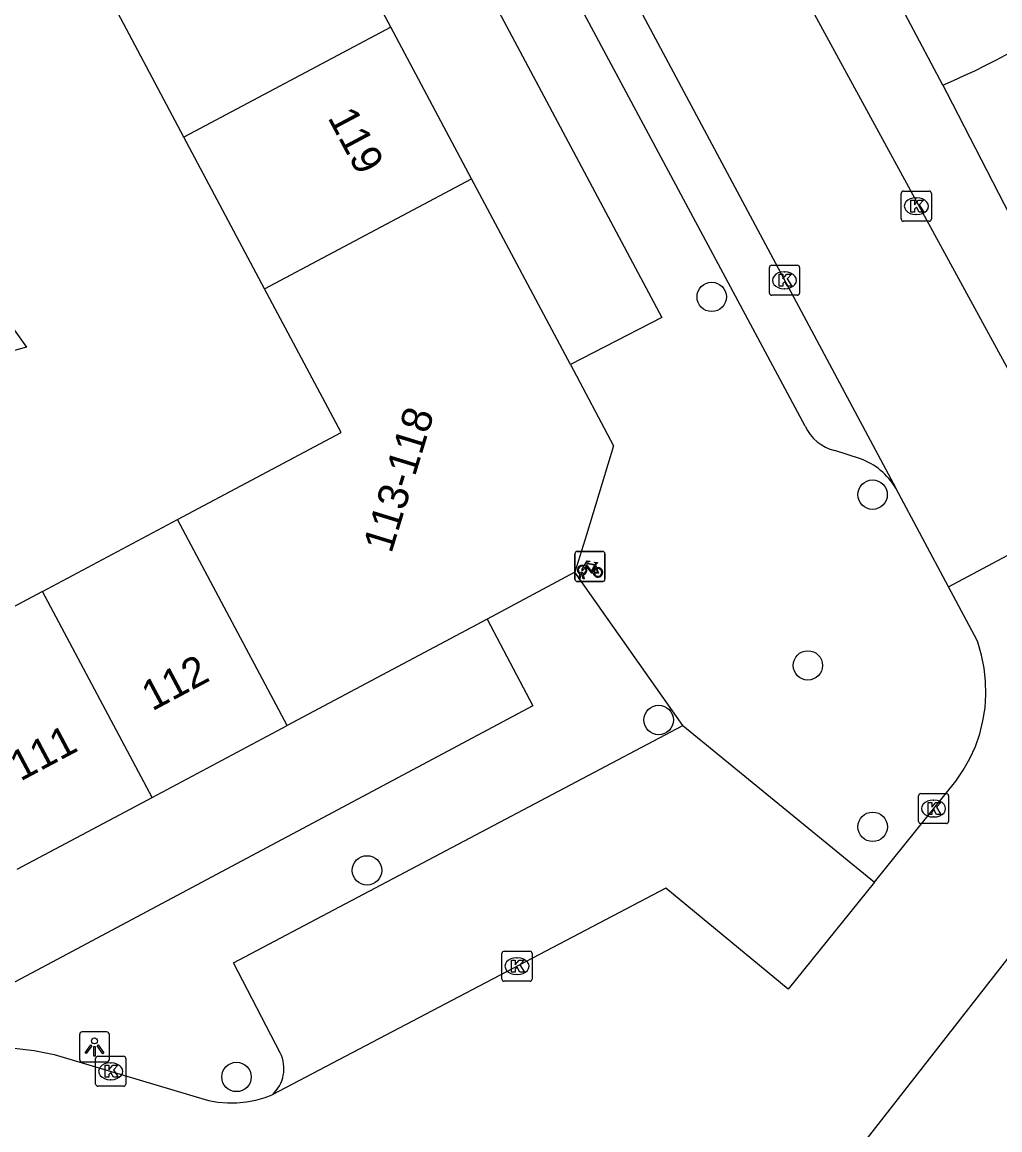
# Model space of a CAD drawing. Extents: x 160304 to 160954, y 383686 to 384161.
# Drawn here: x 160780.26 to 160812.8, y 383795.32 to 383832.18 of the extents above; entities that cross this region are included whole.
import ezdxf

# ---------------------------------------------------------------- set-up
doc = ezdxf.new("R2010")
doc.units = 0
for name, color, linetype in [('IMGEO_Boom', 7, 'Continuous'), ('IMGEO_Fietsenrek', 7, 'Continuous'), ('IMGEO_Kolk', 7, 'Continuous'), ('IMGEO_Lichtpunt', 7, 'Continuous'), ('IMGEO_Pand', 7, 'Continuous'), ('IMGEO_Pand_nummerreeks', 7, 'Continuous'), ('IMGEO_Parkeervlak_open', 7, 'Continuous'), ('IMGEO_Rijbaan_lokaal_open', 7, 'Continuous'), ('IMGEO_Voetpad_open', 7, 'Continuous')]:
    doc.layers.add(name, color=color, linetype=linetype)

msp = doc.modelspace()

# ---------------------------------------------------------------- linework, layer by layer
at = {"layer": 'IMGEO_Boom'}
for centre in [(160803.211, 383823.035), (160808.565, 383816.455), (160806.411, 383810.774), (160801.446, 383808.959), (160808.567, 383805.405), (160791.74, 383803.956), (160787.397, 383797.083)]:
    msp.add_circle(centre, 0.489, dxfattribs=at)
at = {"layer": 'IMGEO_Fietsenrek'}
for p, q in [((160798.659, 383813.642), (160798.659, 383814.483)), ((160798.659, 383814.483), (160798.659, 383813.642)), ((160798.734, 383814.567), (160799.575, 383814.567)), ((160799.575, 383814.567), (160798.734, 383814.567)), ((160799.659, 383814.492), (160799.659, 383813.651)), ((160799.659, 383813.651), (160799.659, 383814.492)), ((160799.346, 383814.116), (160799.382, 383814.021)), ((160798.786, 383813.651), (160798.825, 383813.811)), ((160798.855, 383813.799), (160798.82, 383813.651)), ((160798.897, 383813.823), (160798.896, 383813.827)), ((160798.938, 383813.651), (160798.904, 383813.793)), ((160798.928, 383813.834), (160798.929, 383813.827)), ((160798.936, 383813.797), (160798.971, 383813.651)), ((160799.584, 383813.567), (160798.743, 383813.567)), ((160798.743, 383813.567), (160799.584, 383813.567)), ((160798.82, 383813.651), (160798.786, 383813.651)), ((160798.971, 383813.651), (160798.938, 383813.651))]:
    msp.add_line(p, q, dxfattribs=at)
for points in [[(160798.993, 383814.041), (160798.941, 383813.951), (160798.901, 383813.926), (160798.902, 383813.973), (160798.957, 383814.067)], [(160798.972, 383814.093), (160799.067, 383814.257), (160799.153, 383814.243), (160799.155, 383814.234), (160799.099, 383814.223), (160799.072, 383814.178), (160799.328, 383814.137)], [(160799.268, 383813.849), (160799.218, 383813.849), (160799.027, 383814.1), (160799.008, 383814.068)], [(160799.315, 383814.112), (160799.058, 383814.153), (160799.041, 383814.124), (160799.208, 383813.904), (160799.315, 383814.112)], [(160799.363, 383814.014), (160799.333, 383814.091), (160799.224, 383813.873), (160799.267, 383813.873)], [(160799.328, 383814.137), (160799.353, 383814.186), (160799.347, 383814.19), (160799.324, 383814.194), (160799.312, 383814.201), (160799.311, 383814.204), (160799.313, 383814.209), (160799.408, 383814.194), (160799.41, 383814.184), (160799.4, 383814.171), (160799.388, 383814.165), (160799.374, 383814.171), (160799.346, 383814.116)], [(160799.297, 383813.873), (160799.417, 383813.872), (160799.373, 383813.986)], [(160799.393, 383813.993), (160799.448, 383813.848), (160799.298, 383813.848)]]:
    msp.add_lwpolyline(points, dxfattribs=at)
for centre, radius, start, end in [((160798.737, 383814.489), 0.0779, 92.4484, 184.2845), ((160798.737, 383814.489), 0.0779, 92.4484, 184.2845), ((160799.581, 383814.489), 0.0779, 2.4484, 94.2845), ((160799.581, 383814.489), 0.0779, 2.4484, 94.2845), ((160798.899, 383813.952), 0.159, 62.6766, 242.1369), ((160798.899, 383813.952), 0.129, 63.3192, 238.903), ((160798.899, 383813.952), 0.159, 283.5766, 46.6042), ((160798.879, 383813.823), 0.0499, 12.8025, 158.6934), ((160798.899, 383813.952), 0.159, 253.9967, 271.7867), ((160798.879, 383813.823), 0.0174, 12.8025, 163.4502), ((160798.899, 383813.952), 0.129, 253.415, 269.0204), ((160798.899, 383813.952), 0.129, 283.6043, 43.4302), ((160799.426, 383813.868), 0.159, 113.3408, 178.3217), ((160799.426, 383813.868), 0.159, 187.0065, 105.7708), ((160799.426, 383813.868), 0.129, 113.923, 177.9556), ((160799.426, 383813.868), 0.129, 188.6715, 104.5883), ((160798.737, 383813.645), 0.0779, 182.4484, 274.2845), ((160798.737, 383813.645), 0.0779, 182.4484, 274.2845), ((160799.581, 383813.645), 0.0779, 272.4484, 4.2845), ((160799.581, 383813.645), 0.0779, 272.4484, 4.2845)]:
    msp.add_arc(centre, radius, start, end, dxfattribs=at)
at = {"layer": 'IMGEO_Kolk'}
for p, q in [((160809.52, 383825.628), (160809.52, 383826.48)), ((160809.595, 383826.554), (160810.447, 383826.554)), ((160810.008, 383826.334), (160810.033, 383826.334)), ((160810.521, 383826.48), (160810.521, 383825.628)), ((160810.447, 383825.554), (160809.595, 383825.554)), ((160810.031, 383825.774), (160810.006, 383825.774)), ((160805.132, 383823.162), (160805.132, 383824.014)), ((160805.207, 383824.088), (160806.059, 383824.088)), ((160806.133, 383824.014), (160806.133, 383823.162)), ((160805.62, 383823.868), (160805.645, 383823.868)), ((160805.643, 383823.308), (160805.618, 383823.308)), ((160806.059, 383823.088), (160805.207, 383823.088)), ((160810.094, 383805.586), (160810.094, 383806.438)), ((160810.169, 383806.512), (160811.021, 383806.512)), ((160811.095, 383806.438), (160811.095, 383805.586)), ((160810.582, 383806.292), (160810.607, 383806.292)), ((160810.605, 383805.732), (160810.58, 383805.732)), ((160811.021, 383805.512), (160810.169, 383805.512)), ((160796.231, 383800.342), (160796.231, 383801.194)), ((160796.306, 383801.268), (160797.158, 383801.268)), ((160797.232, 383801.194), (160797.232, 383800.342)), ((160796.719, 383801.048), (160796.744, 383801.048)), ((160796.742, 383800.488), (160796.717, 383800.488)), ((160797.158, 383800.268), (160796.306, 383800.268)), ((160782.71, 383796.846), (160782.71, 383797.698)), ((160782.785, 383797.772), (160783.637, 383797.772)), ((160783.198, 383797.552), (160783.223, 383797.552)), ((160783.711, 383797.698), (160783.711, 383796.846)), ((160783.637, 383796.772), (160782.785, 383796.772)), ((160783.221, 383796.992), (160783.196, 383796.992))]:
    msp.add_line(p, q, dxfattribs=at)
for points in [[(160809.52, 383825.628), (160809.52, 383826.48)], [(160809.595, 383826.554), (160810.447, 383826.554)], [(160809.841, 383826.254), (160809.964, 383826.254), (160809.964, 383826.103), (160810.094, 383826.254), (160810.258, 383826.254), (160810.112, 383826.103), (160810.265, 383825.854), (160810.113, 383825.854), (160810.028, 383826.018), (160809.964, 383825.951), (160809.964, 383825.854), (160809.841, 383825.854), (160809.841, 383826.254)], [(160810.521, 383826.48), (160810.521, 383825.628)], [(160810.447, 383825.554), (160809.595, 383825.554)], [(160805.132, 383823.162), (160805.132, 383824.014)], [(160805.207, 383824.088), (160806.059, 383824.088)], [(160806.133, 383824.014), (160806.133, 383823.162)], [(160805.453, 383823.788), (160805.576, 383823.788), (160805.576, 383823.637), (160805.706, 383823.788), (160805.87, 383823.788), (160805.724, 383823.637), (160805.877, 383823.388), (160805.725, 383823.388), (160805.64, 383823.552), (160805.576, 383823.485), (160805.576, 383823.388), (160805.453, 383823.388), (160805.453, 383823.788)], [(160806.059, 383823.088), (160805.207, 383823.088)], [(160810.094, 383805.586), (160810.094, 383806.438)], [(160810.169, 383806.512), (160811.021, 383806.512)], [(160811.095, 383806.438), (160811.095, 383805.586)], [(160810.415, 383806.212), (160810.538, 383806.212), (160810.538, 383806.061), (160810.668, 383806.212), (160810.832, 383806.212), (160810.686, 383806.061), (160810.839, 383805.812), (160810.687, 383805.812), (160810.602, 383805.976), (160810.538, 383805.909), (160810.538, 383805.812), (160810.415, 383805.812), (160810.415, 383806.212)], [(160811.021, 383805.512), (160810.169, 383805.512)], [(160796.231, 383800.342), (160796.231, 383801.194)], [(160796.306, 383801.268), (160797.158, 383801.268)], [(160797.232, 383801.194), (160797.232, 383800.342)], [(160796.552, 383800.968), (160796.675, 383800.968), (160796.675, 383800.817), (160796.805, 383800.968), (160796.969, 383800.968), (160796.823, 383800.817), (160796.976, 383800.568), (160796.824, 383800.568), (160796.739, 383800.732), (160796.675, 383800.665), (160796.675, 383800.568), (160796.552, 383800.568), (160796.552, 383800.968)], [(160797.158, 383800.268), (160796.306, 383800.268)], [(160782.71, 383796.846), (160782.71, 383797.698)], [(160782.785, 383797.772), (160783.637, 383797.772)], [(160783.031, 383797.472), (160783.154, 383797.472), (160783.154, 383797.321), (160783.284, 383797.472), (160783.448, 383797.472), (160783.302, 383797.321), (160783.455, 383797.072), (160783.303, 383797.072), (160783.218, 383797.236), (160783.154, 383797.169), (160783.154, 383797.072), (160783.031, 383797.072), (160783.031, 383797.472)], [(160783.711, 383797.698), (160783.711, 383796.846)], [(160783.637, 383796.772), (160782.785, 383796.772)]]:
    msp.add_lwpolyline(points, dxfattribs=at)
for centre, start, end in [((160809.597, 383826.478), 91.552, 178.448), ((160809.597, 383826.478), 91.552, 178.448), ((160810.445, 383826.478), 1.552, 88.448), ((160810.445, 383826.478), 1.552, 88.448), ((160809.597, 383825.63), 181.552, 268.448), ((160809.597, 383825.63), 181.552, 268.448), ((160810.445, 383825.63), 271.552, 358.448), ((160810.445, 383825.63), 271.552, 358.448), ((160805.209, 383824.012), 91.552, 178.448), ((160805.209, 383824.012), 91.552, 178.448), ((160806.057, 383824.012), 1.552, 88.448), ((160806.057, 383824.012), 1.552, 88.448), ((160805.209, 383823.164), 181.552, 268.448), ((160805.209, 383823.164), 181.552, 268.448), ((160806.057, 383823.164), 271.552, 358.448), ((160806.057, 383823.164), 271.552, 358.448), ((160810.171, 383806.436), 91.552, 178.448), ((160810.171, 383806.436), 91.552, 178.448), ((160811.019, 383806.436), 1.552, 88.448), ((160811.019, 383806.436), 1.552, 88.448), ((160810.171, 383805.588), 181.552, 268.448), ((160810.171, 383805.588), 181.552, 268.448), ((160811.019, 383805.588), 271.552, 358.448), ((160811.019, 383805.588), 271.552, 358.448), ((160796.308, 383801.192), 91.552, 178.448), ((160796.308, 383801.192), 91.552, 178.448), ((160797.156, 383801.192), 1.552, 88.448), ((160797.156, 383801.192), 1.552, 88.448), ((160796.308, 383800.344), 181.552, 268.448), ((160796.308, 383800.344), 181.552, 268.448), ((160797.156, 383800.344), 271.552, 358.448), ((160797.156, 383800.344), 271.552, 358.448), ((160782.787, 383797.696), 91.552, 178.448), ((160782.787, 383797.696), 91.552, 178.448), ((160783.635, 383797.696), 1.552, 88.448), ((160783.635, 383797.696), 1.552, 88.448), ((160782.787, 383796.848), 181.552, 268.448), ((160782.787, 383796.848), 181.552, 268.448), ((160783.635, 383796.848), 271.552, 358.448), ((160783.635, 383796.848), 271.552, 358.448)]:
    msp.add_arc(centre, 0.0765, start, end, dxfattribs=at)
for centre, major_axis, ratio, start_param, end_param in [((160810.007, 383826.054), (-0.387, 0.002), 0.722429, 4.712389, 7.853982), ((160810.032, 383826.054), (-0.39, 0.002), 0.717154, 1.570796, 4.712389), ((160805.619, 383823.588), (-0.387, 0.002), 0.722429, 4.712389, 7.853982), ((160805.644, 383823.588), (-0.39, 0.002), 0.717154, 1.570796, 4.712389), ((160810.581, 383806.012), (-0.387, 0.002), 0.722429, 4.712389, 7.853982), ((160810.606, 383806.012), (-0.39, 0.002), 0.717154, 1.570796, 4.712389), ((160796.718, 383800.768), (-0.387, 0.002), 0.722429, 4.712389, 7.853982), ((160796.743, 383800.768), (-0.39, 0.002), 0.717154, 1.570796, 4.712389), ((160783.197, 383797.272), (-0.387, 0.002), 0.722429, 4.712389, 7.853982), ((160783.222, 383797.272), (-0.39, 0.002), 0.717154, 1.570796, 4.712389)]:
    msp.add_ellipse(centre, major_axis=major_axis, ratio=ratio, start_param=start_param, end_param=end_param, dxfattribs=at)
at = {"layer": 'IMGEO_Lichtpunt'}
for p, q in [((160783.074, 383798.58), (160782.266, 383798.58)), ((160783.074, 383798.58), (160782.266, 383798.58)), ((160782.172, 383798.485), (160782.172, 383797.678)), ((160782.172, 383798.485), (160782.172, 383797.678)), ((160783.168, 383797.678), (160783.168, 383798.485)), ((160783.168, 383797.678), (160783.168, 383798.485)), ((160782.266, 383797.584), (160783.074, 383797.584)), ((160782.266, 383797.584), (160783.074, 383797.584))]:
    msp.add_line(p, q, dxfattribs=at)
for points in [[(160782.546, 383798.149), (160782.585, 383798.121), (160782.397, 383797.859), (160782.359, 383797.886), (160782.546, 383798.149)], [(160782.648, 383798.101), (160782.695, 383798.101), (160782.695, 383797.779), (160782.648, 383797.779), (160782.648, 383798.101)], [(160782.758, 383798.121), (160782.796, 383798.148), (160782.983, 383797.886), (160782.944, 383797.858), (160782.758, 383798.121)]]:
    msp.add_lwpolyline(points, dxfattribs=at)
msp.add_circle((160782.671, 383798.283), 0.0994, dxfattribs=at)
for centre, start, end in [((160782.266, 383798.485), 90, 180), ((160782.266, 383798.485), 90, 180), ((160783.074, 383798.485), 0, 90), ((160783.074, 383798.485), 0, 90), ((160782.266, 383797.678), 180, 270), ((160782.266, 383797.678), 180, 270), ((160783.074, 383797.678), 270, 0), ((160783.074, 383797.678), 270, 360)]:
    msp.add_arc(centre, 0.0946, start, end, dxfattribs=at)
at = {"layer": 'IMGEO_Pand'}
for points in [[(160792.531, 383832.012), (160789.847, 383837.056)], [(160785.65, 383828.349), (160782.966, 383833.394)], [(160792.531, 383832.012), (160785.65, 383828.349)], [(160795.216, 383826.967), (160792.531, 383832.012)], [(160788.334, 383823.305), (160785.65, 383828.349)], [(160788.334, 383823.305), (160795.216, 383826.967)], [(160798.507, 383820.783), (160795.216, 383826.967)], [(160785.435, 383815.628), (160790.878, 383818.524), (160788.334, 383823.305)], [(160798.507, 383820.783), (160799.945, 383818.08), (160799.566, 383816.837), (160799.04, 383815.116), (160798.66, 383813.873)], [(160780.945, 383813.238), (160785.435, 383815.628)], [(160789.081, 383808.776), (160785.435, 383815.628)], [(160798.66, 383813.873), (160795.736, 383812.317)], [(160780.945, 383813.238), (160776.454, 383810.849)], [(160784.591, 383806.386), (160780.945, 383813.238)], [(160795.736, 383812.317), (160789.081, 383808.776)], [(160784.591, 383806.386), (160789.081, 383808.776)], [(160780.1, 383803.997), (160784.591, 383806.386)]]:
    msp.add_lwpolyline(points, dxfattribs=at)
at = {"layer": 'IMGEO_Parkeervlak_open'}
msp.add_arc((160801.876, 383851.692), 23.416, 292.6652, 323.0134, dxfattribs=at)
at = {"layer": 'IMGEO_Rijbaan_lokaal_open'}
for points in [[(160785.169, 383861.857), (160809.333, 383816.673)], [(160806.296, 383833.052), (160815.679, 383815.845)], [(160811.089, 383813.39), (160809.333, 383816.673)], [(160811.089, 383813.39), (160815.679, 383815.845)], [(160808.625, 383803.562), (160811.332, 383806.927), (160811.583, 383807.291), (160811.801, 383807.676), (160811.984, 383808.079), (160812.129, 383808.497), (160812.237, 383808.926), (160812.306, 383809.363), (160812.336, 383809.804), (160812.326, 383810.246), (160812.277, 383810.686), (160812.189, 383811.119), (160812.062, 383811.543), (160812.034, 383811.622), (160811.089, 383813.39)], [(160808.625, 383803.562), (160805.76, 383800), (160801.684, 383803.365), (160788.583, 383796.488)], [(160802.2, 383787.125), (160813.631, 383801.743)], [(160773.535, 383795.135), (160773.968, 383795.648), (160774.444, 383796.12), (160774.962, 383796.548), (160775.515, 383796.927), (160776.1, 383797.256), (160776.712, 383797.532), (160777.347, 383797.751), (160777.998, 383797.913), (160778.661, 383798.016), (160779.331, 383798.06), (160780.002, 383798.043), (160780.669, 383797.967), (160781.326, 383797.831), (160786.462, 383796.304), (160786.776, 383796.249), (160787.094, 383796.223), (160787.412, 383796.225), (160787.73, 383796.256), (160788.043, 383796.315), (160788.35, 383796.402), (160788.583, 383796.488)]]:
    msp.add_lwpolyline(points, dxfattribs=at)
at = {"layer": 'IMGEO_Voetpad_open'}
for points in [[(160806.317, 383818.739), (160786.477, 383855.764)], [(160784.351, 383854.625), (160801.546, 383822.346), (160798.507, 383820.783)], [(160810.899, 383830.084), (160808.576, 383834.484)], [(160810.899, 383830.084), (160811.03, 383829.829), (160817.702, 383816.886)], [(160778.732, 383822.62), (160779.699, 383822.36), (160780.408, 383821.364), (160779.047, 383820.981), (160778.174, 383821.209), (160774.617, 383822.188), (160771.459, 383823.057)], [(160808.157, 383817.646), (160807.307, 383817.926)], [(160802.245, 383808.778), (160798.66, 383813.873)], [(160795.736, 383812.317), (160797.261, 383809.435), (160772.561, 383796.263)], [(160788.852, 383797.884), (160787.294, 383800.881), (160802.245, 383808.778)], [(160802.245, 383808.778), (160808.625, 383803.562)]]:
    msp.add_lwpolyline(points, dxfattribs=at)
for centre, radius, start, end in [((160807.635, 383819.335), 1.446, 204.3225, 256.8909), ((160807.438, 383815.579), 2.188, 29.9866, 70.806), ((160787.811, 383797.361), 1.165, 311.5042, 26.6822)]:
    msp.add_arc(centre, radius, start, end, dxfattribs=at)

# ---------------------------------------------------------------- texts
at = {"layer": 'IMGEO_Pand_nummerreeks'}
for s, rotation, p in [('119', 298.0189, (160790.417, 383829.003)), ('113-118', 73.0063, (160792.55, 383814.473)), ('112', 28.0217, (160784.593, 383809.242)), ('111', 28.0176, (160780.206, 383806.907))]:
    msp.add_text(s, height=1, rotation=rotation, dxfattribs=at).set_placement(p)

doc.saveas('drawing.dxf')
